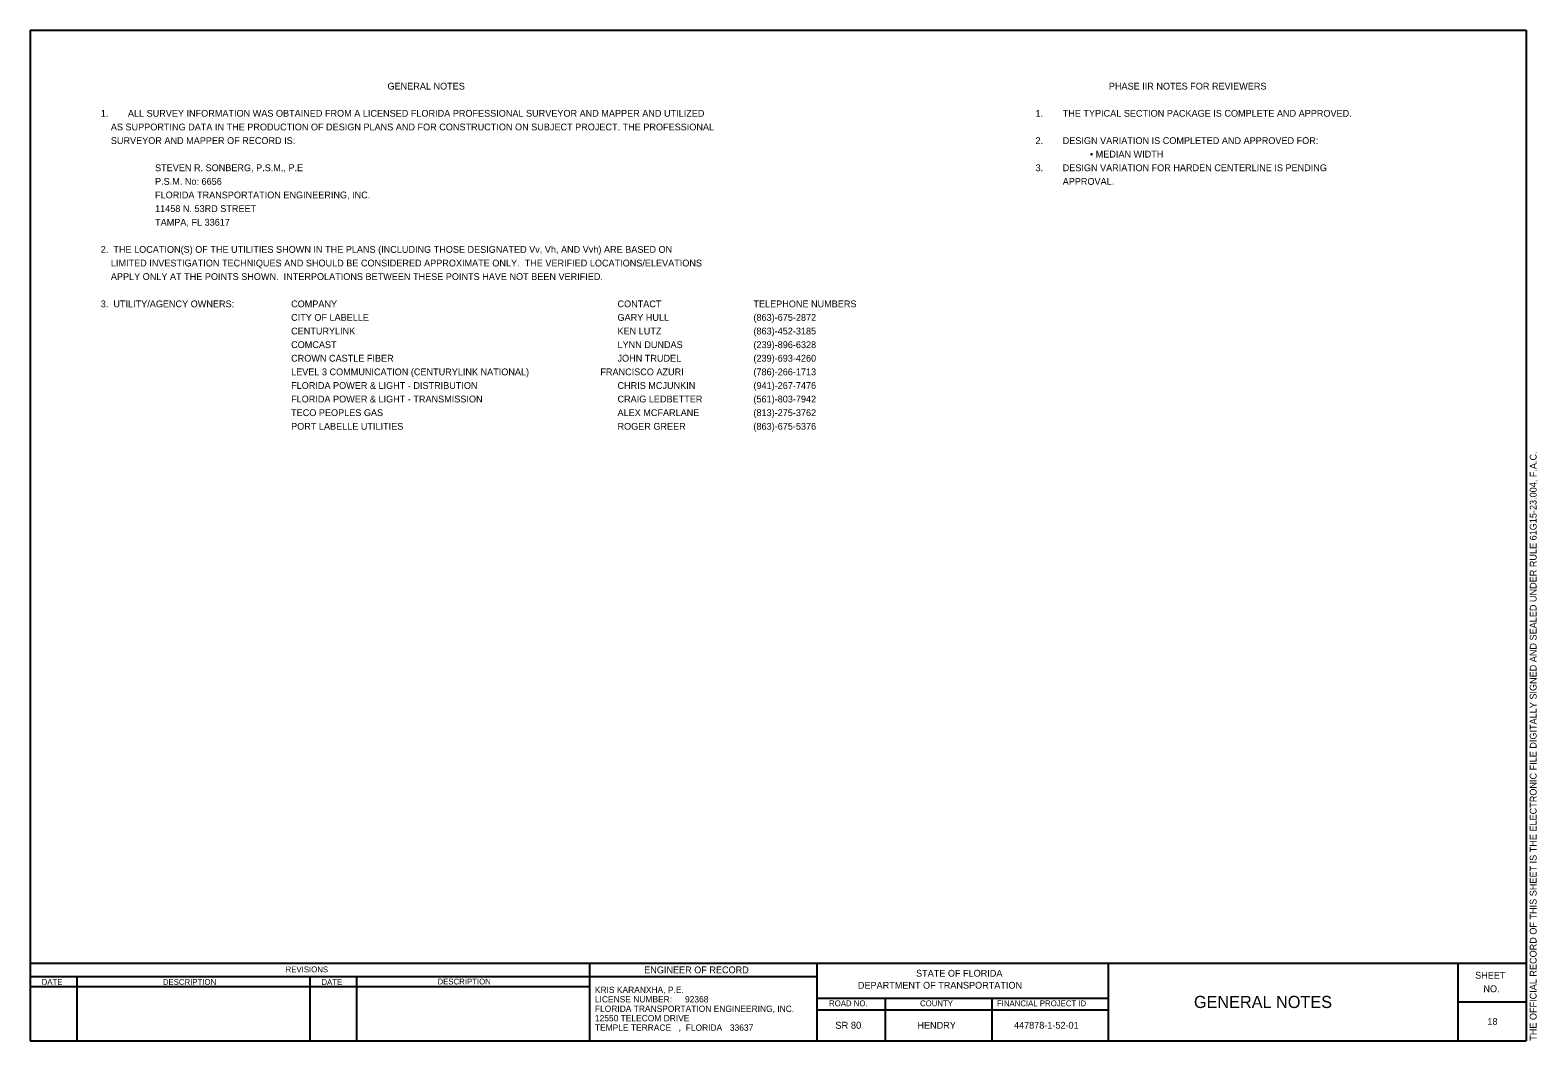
# Model space of a CAD drawing. Extents: x -0.81 to 1.34, y 0 to 0.87.
# Drawn here: x 0.046 to 1.339, y 0.004 to 0.871 of the extents above; entities that cross this region are included whole.
import ezdxf

# ---------------------------------------------------------------- set-up
doc = ezdxf.new("R2010")
doc.units = 0
for name, color, linetype in [('SheetBorder_dp', 7, 'Continuous'), ('SheetLines_dp', 7, 'Continuous'), ('TextMisc', 7, 'Continuous'), ('TextNotes', 7, 'Continuous'), ('TextShtNo', 7, 'Continuous')]:
    doc.layers.add(name, color=color, linetype=linetype)

msp = doc.modelspace()

# ---------------------------------------------------------------- linework, layer by layer
at = {"layer": 'SheetBorder_dp'}
for p, q in [((0.0458, 0.8708), (0.0458, 0.0042)), ((0.0458, 0.8708), (1.3292, 0.8708)), ((1.3292, 0.8708), (1.3292, 0.0042)), ((0.0458, 0.0708), (1.3292, 0.0708)), ((0.0458, 0.0042), (1.3292, 0.0042))]:
    msp.add_line(p, q, dxfattribs=at)
at = {"layer": 'SheetLines_dp'}
for p, q in [((0.5258, 0.0708), (0.5258, 0.0042)), ((0.7208, 0.0708), (0.7208, 0.0042)), ((0.9708, 0.0042), (0.9708, 0.0708)), ((1.2708, 0.0042), (1.2708, 0.0708)), ((0.0458, 0.0592), (0.5258, 0.0592)), ((0.0858, 0.0592), (0.0858, 0.0042)), ((0.2858, 0.0592), (0.2858, 0.0042)), ((0.3258, 0.0592), (0.3258, 0.0042)), ((0.5262, 0.0592), (0.7208, 0.0592)), ((0.0458, 0.0508), (0.5258, 0.0508)), ((0.7208, 0.0408), (0.9708, 0.0408)), ((0.7792, 0.0408), (0.7792, 0.0042)), ((0.8708, 0.0408), (0.8708, 0.0042)), ((0.7208, 0.0308), (0.9708, 0.0308)), ((1.2708, 0.0375), (1.3292, 0.0375))]:
    msp.add_line(p, q, dxfattribs=at)

# ---------------------------------------------------------------- texts
at = {"layer": 'TextMisc'}
for s, height, rotation, p in [('THE OFFICIAL RECORD OF THIS SHEET IS THE ELECTRONIC FILE DIGITALLY SIGNED AND SEALED UNDER RULE 61G15-23.004, F.A.C.', 0.0058333, 90, (1.3381, 0.0042)), ('DATE', 0.005, 359.8693, (0.0557, 0.0522)), ('DESCRIPTION', 0.005, 0.0498, (0.1597, 0.0521)), ('DATE', 0.005, 359.8693, (0.2957, 0.0521)), ('DESCRIPTION', 0.005, 0.0498, (0.3953, 0.0525)), ('SHEET', 0.00583, 359.8607, (1.2854, 0.0575)), ('NO.', 0.00583, 359.8607, (1.2925, 0.0459))]:
    msp.add_text(s, height=height, rotation=rotation, dxfattribs=at).set_placement(p)
for s, height, p in [('REVISIONS', 0.005, (0.265, 0.0629)), ('ENGINEER OF RECORD', 0.005833, (0.5726, 0.0621)), ('STATE OF FLORIDA', 0.005833, (0.8058, 0.0592)), ('DEPARTMENT OF TRANSPORTATION', 0.005833, (0.7559, 0.0489)), ('KRIS KARANXHA, P.E.', 0.0054, (0.5303, 0.0452)), ('LICENSE NUMBER: ', 0.0054, (0.5303, 0.0371)), ('92368', 0.0054, (0.6076, 0.0371)), ('ROAD NO.', 0.005, (0.7312, 0.0338)), ('COUNTY', 0.005, (0.8092, 0.0338)), ('FINANCIAL PROJECT ID', 0.005, (0.8752, 0.0338)), ('GENERAL NOTES', 0.010417, (1.0442, 0.0323)), ('12550 TELECOM DRIVE', 0.0054, (0.5303, 0.0209)), ('FLORIDA TRANSPORTATION ENGINEERING, INC.', 0.0054, (0.5303, 0.029)), ('TEMPLE TERRACE', 0.0054, (0.5303, 0.0128)), (', ', 0.0054, (0.6021, 0.0128)), ('FLORIDA', 0.0054, (0.6082, 0.0128)), ('33637', 0.0054, (0.6461, 0.0128)), ('SR 80', 0.006, (0.7365, 0.0145)), ('HENDRY', 0.00583, (0.807, 0.0146)), ('447878-1-52-01', 0.005833, (0.8898, 0.0146))]:
    msp.add_text(s, height=height, dxfattribs=at).set_placement(p)
at = {"layer": 'TextNotes'}
for s, height, p in [('GENERAL NOTES', 0.005833, (0.3524, 0.8199)), ('PHASE IIR NOTES FOR REVIEWERS', 0.005833, (0.9712, 0.8199)), ('1.', 0.00583, (0.1064, 0.7966)), ('ALL SURVEY INFORMATION WAS OBTAINED FROM A LICENSED FLORIDA PROFESSIONAL SURVEYOR AND MAPPER AND UTILIZED ', 0.0058331, (0.1297, 0.7966)), ('1.', 0.00583, (0.9083, 0.7966)), ('THE TYPICAL SECTION PACKAGE IS COMPLETE AND APPROVED.', 0.005833, (0.9316, 0.7966)), ('    AS SUPPORTING DATA IN THE PRODUCTION OF DESIGN PLANS AND FOR CONSTRUCTION ON SUBJECT PROJECT. THE PROFESSIONAL', 0.0058331, (0.1064, 0.7849)), ('    SURVEYOR AND MAPPER OF RECORD IS:', 0.005833, (0.1064, 0.7732)), ('2.', 0.00583, (0.9083, 0.7732)), ('DESIGN VARIATION IS COMPLETED AND APPROVED FOR:', 0.005833, (0.9316, 0.7732)), ('• MEDIAN WIDTH', 0.005833, (0.955, 0.7616)), ('STEVEN R. SONBERG, P.S.M., P.E', 0.005833, (0.153, 0.7499)), ('3.', 0.00583, (0.9083, 0.7499)), ('DESIGN VARIATION FOR HARDEN CENTERLINE IS PENDING', 0.005833, (0.9316, 0.7499)), ('P.S.M. No: 6656', 0.005833, (0.153, 0.7382)), ('APPROVAL.', 0.00583, (0.9316, 0.7382)), ('FLORIDA TRANSPORTATION ENGINEERING, INC.', 0.005833, (0.153, 0.7266)), ('11458 N. 53RD STREET', 0.005833, (0.153, 0.7149)), ('TAMPA, FL 33617', 0.005833, (0.153, 0.7032)), ('2.  THE LOCATION(S) OF THE UTILITIES SHOWN IN THE PLANS (INCLUDING THOSE DESIGNATED Vv, Vh, AND Vvh) ARE BASED ON ', 0.0058331, (0.1064, 0.6799)), ('    LIMITED INVESTIGATION TECHNIQUES AND SHOULD BE CONSIDERED APPROXIMATE ONLY.  THE VERIFIED LOCATIONS/ELEVATIONS ', 0.0058331, (0.1064, 0.6682)), ('    APPLY ONLY AT THE POINTS SHOWN.  INTERPOLATIONS BETWEEN THESE POINTS HAVE NOT BEEN VERIFIED.', 0.005833, (0.1064, 0.6566)), ('3.  UTILITY/AGENCY OWNERS: ', 0.005833, (0.1064, 0.6332)), ('COMPANY', 0.00583, (0.2697, 0.6332)), ('CONTACT', 0.00583, (0.5497, 0.6332)), ('TELEPHONE NUMBERS', 0.005833, (0.6663, 0.6332)), ('CITY OF LABELLE', 0.005833, (0.2697, 0.6216)), ('GARY HULL', 0.00583, (0.5497, 0.6216)), ('(863)-675-2872', 0.005833, (0.6663, 0.6216)), ('CENTURYLINK        ', 0.005833, (0.2697, 0.6099)), ('KEN LUTZ', 0.00583, (0.5497, 0.6099)), ('(863)-452-3185', 0.005833, (0.6663, 0.6099)), ('COMCAST', 0.00583, (0.2697, 0.5982)), ('LYNN DUNDAS', 0.005833, (0.5497, 0.5982)), ('(239)-896-6328', 0.005833, (0.6663, 0.5982)), ('CROWN CASTLE FIBER', 0.005833, (0.2697, 0.5866)), ('JOHN TRUDEL', 0.005833, (0.5497, 0.5866)), ('(239)-693-4260', 0.005833, (0.6663, 0.5866)), ('LEVEL 3 COMMUNICATION (CENTURYLINK NATIONAL)', 0.005833, (0.2697, 0.5749)), ('FLORIDA POWER & LIGHT - DISTRIBUTION', 0.005833, (0.2697, 0.5632)), ('    FRANCISCO AZURI', 0.005833, (0.5263, 0.5749)), ('CHRIS MCJUNKIN', 0.005833, (0.5497, 0.5632)), ('(786)-266-1713', 0.005833, (0.6663, 0.5749)), ('(941)-267-7476', 0.005833, (0.6663, 0.5632)), ('FLORIDA POWER & LIGHT - TRANSMISSION', 0.005833, (0.2697, 0.5516)), ('CRAIG LEDBETTER', 0.005833, (0.5497, 0.5516)), ('(561)-803-7942', 0.005833, (0.6663, 0.5516)), ('TECO PEOPLES GAS', 0.005833, (0.2697, 0.5399)), ('ALEX MCFARLANE', 0.005833, (0.5497, 0.5399)), ('(813)-275-3762', 0.005833, (0.6663, 0.5399)), ('PORT LABELLE UTILITIES', 0.005833, (0.2697, 0.5282)), ('ROGER GREER', 0.005833, (0.5497, 0.5282)), ('(863)-675-5376', 0.005833, (0.6663, 0.5282))]:
    msp.add_text(s, height=height, dxfattribs=at).set_placement(p)
at = {"layer": 'TextShtNo'}
msp.add_text('18', height=0.00583, dxfattribs=at).set_placement((1.2959, 0.0179))

doc.saveas('drawing.dxf')
